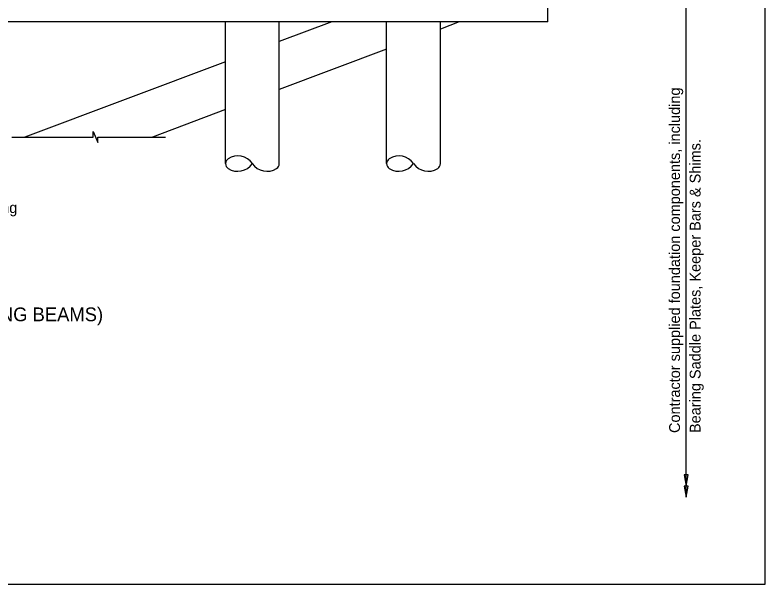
# Model space of a CAD drawing. Extents: x 11137.4 to 11208.2, y 76297.7 to 76332.4.
# Drawn here: x 11164.53 to 11178.49, y 76306.21 to 76316.8 of the extents above; entities that cross this region are included whole.
import ezdxf

# ---------------------------------------------------------------- set-up
doc = ezdxf.new("R2010")
doc.units = 0
for name, color, linetype in [('ActivePts-ConstElements', 7, 'Continuous'), ('Dimension', 7, 'Continuous'), ('Symbols', 7, 'Continuous'), ('TextStructures', 7, 'Continuous'), ('Wood', 7, 'Continuous')]:
    doc.layers.add(name, color=color, linetype=linetype)

msp = doc.modelspace()

# ---------------------------------------------------------------- linework, layer by layer
at = {"layer": 'ActivePts-ConstElements'}
msp.add_lwpolyline([(11137.439, 76306.213), (11178.49, 76306.213), (11178.49, 76332.159), (11137.439, 76332.159)], close=True, dxfattribs=at)
at = {"layer": 'Dimension'}
msp.add_line((11177.021, 76307.827), (11177.021, 76326.25), dxfattribs=at)
for points in [[(11177.021, 76308.035), (11177.057, 76308.243), (11176.986, 76308.243)], [(11177.021, 76307.827), (11177.057, 76308.035), (11176.986, 76308.035)]]:
    msp.add_lwpolyline(points, close=True, dxfattribs=at)
at = {"layer": 'Symbols'}
msp.add_lwpolyline([(11164.465, 76314.531), (11165.982, 76314.531), (11165.982, 76314.634), (11166.072, 76314.427), (11166.072, 76314.531), (11167.33, 76314.531)], dxfattribs=at)
at = {"layer": 'Wood'}
for p, q in [((11174.446, 76316.673), (11174.446, 76317.673)), ((11174.446, 76316.673), (11158.04, 76316.673)), ((11168.446, 76314.036), (11168.446, 76316.673)), ((11170.426, 76316.673), (11169.446, 76316.306)), ((11169.446, 76314.036), (11169.446, 76316.673)), ((11171.446, 76314.036), (11171.446, 76316.673)), ((11172.799, 76316.673), (11172.446, 76316.541)), ((11172.446, 76314.036), (11172.446, 76316.673)), ((11171.446, 76316.166), (11169.446, 76315.416)), ((11168.446, 76315.931), (11164.713, 76314.531)), ((11168.446, 76315.041), (11167.086, 76314.531))]:
    msp.add_line(p, q, dxfattribs=at)
for centre, radius, start, end in [((11168.674, 76313.851), 0.329, 34.3251, 123.0426), ((11171.674, 76313.851), 0.329, 34.3251, 123.0426), ((11168.553, 76314.036), 0.107, 122.6152, 179.9979), ((11168.553, 76314.036), 0.107, 179.9979, 237.3848), ((11168.674, 76314.222), 0.329, 236.955, 325.6725), ((11169.217, 76314.222), 0.329, 214.3153, 303.0328), ((11169.339, 76314.036), 0.107, 302.6152, 0.0021), ((11171.553, 76314.036), 0.107, 122.6152, 179.9979), ((11171.553, 76314.036), 0.107, 179.9979, 237.3848), ((11171.674, 76314.222), 0.329, 236.955, 325.6725), ((11172.217, 76314.222), 0.329, 214.3153, 303.0328), ((11172.339, 76314.036), 0.107, 302.6152, 0.0021)]:
    msp.add_arc(centre, radius, start, end, dxfattribs=at)

# ---------------------------------------------------------------- texts
at = {"layer": 'TextStructures'}
for s, p in [('Contractor supplied foundation components, including ', (11176.907, 76309.023)), ('Bearing Saddle Plates, Keeper Bars & Shims.', (11177.29, 76309.023))]:
    msp.add_text(s, height=0.2016, rotation=90, dxfattribs=at).set_placement(p)
for s, height, p in [('Pile sizes and spacing, bent cap and bracing ', 0.2016, (11159.235, 76313.115)), ('TYPICAL SECTION THRU DETOUR BRIDGE AT INTERIOR BENTS (TYPICAL SECTION AT END BENTS SIMILAR WITHOUT DISTRIBUTING BEAMS)', 0.256001, (11142.715, 76311.103))]:
    msp.add_text(s, height=height, dxfattribs=at).set_placement(p)

doc.saveas('drawing.dxf')
